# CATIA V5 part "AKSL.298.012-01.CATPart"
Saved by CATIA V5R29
Part number: АКСЛ.298.012-01
Publications: "Грань по длине шипа", "Грань по ширине шипа", "Грань по длине шипа1", "Грань по ширине шипа1"
Material "Steel": density 7860 kg/m3, Young's modulus 2e+11 Pa, Poisson ratio 0.266, thermal expansion 1.17e-05 1/K
Bounding box of the stored display mesh (mm): x -51 to 52, y -52 to 51, z -103 to 100
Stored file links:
  Z:\ООО Аксель\Соединения бруса\Соединения бруса\Соединения из листа\АКСЛ.298.010 (Основание)\AKSL.298.012-01.CATPart
  Z:\ООО Аксель\Соединения бруса\Соединения бруса\Соединения из листа\АКСЛ.298.010 (Основание)\AKSL.298.010.CATProduct
  Z:\#Catalog_GosNIIAS\Holes&Pockets\Part\Соединение шип-паз\Ship-Paz.CATPart
  298.012.CATPart
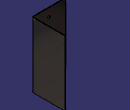
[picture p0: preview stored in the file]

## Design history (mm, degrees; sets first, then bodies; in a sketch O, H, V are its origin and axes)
External parameters (linked from other documents)
  `External.S металла` = 2 mm
  `External.R гиба` = 1.9 mm
  `External.K-factor` = 0.49
SheetMetalParameters1: Thickness 2 {= `External.S металла`}, BendRadius 1.9 {= `External.R гиба`}, KFactor 0.49 {= `External.K-factor`}, ReliefRadialLength 1, ReliefAxialLength 2, MinimumBendRadius 0
Set1 "Шип в центре грани"
  Extract1 "Плоскость шипа": ExtractElem face of Wall1
  Extract2 "Грань по длине шипа": ExtractElem edge of Extract1
  Extract3 "Грань по ширине шипа": ExtractElem edge of Extract1
Set2
  DatumCurve1 to DatumCurve3: linked copy from another document
  Plane1: linked copy from another document
Body1 (main body)
  Pad1: profile DatumCurve1, length 203, opposite side length -3, thin wall 0, second thickness 2 {= `External.S металла`}
  Recognize1: Recognize_BendTable SheetMetalParameters1, Recognize_ReferenceFace face of Pad1, Recognize_BendDefaultRadius 1.9 {= `External.R гиба`}, KFacteur 0.49 {= SheetMetalParameters1.KFactor}
  d_Bend1: Bend_BendTable SheetMetalParameters1, Bend_Thickness 2 {= `External.S металла`}, Bend_KFactor 0.49 {= SheetMetalParameters1.KFactor}, Bend_FirstSupport face of Recognize1, Bend_SecondSupport face of Recognize1, Bend_KFactorRadius 1.9 {= d_Bend1.CylindricalBendSurf_Radius}, Bend_Deduction -3.2761 {= (d_Bend1.CylindricalBendSurf_Radius+SheetMetalParameters1.Thickness*d_Bend1.Bend_KFactor)*(PI-abs(d_Bend1.BendSurf_OpenAngle))-2*(d_Bend1.CylindricalBendSurf_Radius+SheetMetalParameters1.Thickness)*tan(min((PI-abs(d_Bend1.BendSurf_OpenAngle)),(PI/2))/2)}
  CutOut1: Direction Sketch3, EndLimit through (limit type 2), Orientation true, Profile Sketch3, StartLimit through (limit type 2)
  CutOut2: Direction Sketch2, EndLimit through (limit type 2), Orientation true, Profile Sketch2, StartLimit through (limit type 2), Thickness1 2, Thickness2 2
  SHM_Mirror1: MirroringPlane Plane1, ObjectToMirror CutOut2
  Sketch1 on face of Recognize1, origin (13.3256, -52, 70.7942), H (1, 0, 0), V (0, 0, 1)
    point P1 (-12.3256, 4.2058)
    reference projected line E1 (-63.3256, -170.7942) -> (-63.3256, 29.2058) from edge [face of Recognize1 | face of Recognize1]
    reference projected line E2 (38.6744, -170.7942) -> (38.6744, 29.2058) from face of Recognize1
    construction line L1 (-63.3256, 29.2058) -> (38.6744, 29.2058)
    distance L1 P1 = 25
    horizontal: L1 H
    equidistance: E1 E2 P1
  Hole1: placed by Sketch1, at (1, -52, 75) direction (0, 1, 0), diameter 8, through (limit type 6)
  RectPattern1: of Hole1, direction 1 instances 3, spacing 50, along edge [face of Recognize1 | face of Recognize1] reversed
  Wall1: Thickness 2 {= `External.S металла`}, Profile Sketch4, ListTangentTo face of Recognize1, OffsetValue 0
  Wall2: Thickness 2 {= `External.S металла`}, Profile Sketch5, ListTangentTo face of Recognize1, OffsetValue 0
  Sketch2 on face of Recognize1, origin (52, 0, 0), H (0, 1, 0), V (0, 0, 1)
    reference projected line E2 (52, 100) -> (-48.1, 100) from edge [face of Recognize1 | face of Recognize1]
    point P5 (50, 90.5)
    point P6 (52, 90.5)
    construction line L1 (52, 100) -> (52, 90.5)
    line L2 (52, 90.5) -> (51, 90.5)
    line L3 (51, 90.5) -> (51, 100)
    line L4 (51, 100) -> (52, 100)
    line L5 (52, 100) -> (52, 90.5)
    point P8 (51, 100)
    vertical: L1 V, L3 V, L5 V
    horizontal: L2 H, L4 H
    coincidence: P8 E2
    symmetry: P5 P6 L3
  Sketch3 on DatumCurve2, origin (51, 50, 90), H (0, 0, -1), V (0, -1, 0)
    reference projected line E1 (0, -2) -> (0, 0) from DatumCurve3
    reference projected line E2 (0, 0) -> (180, 0) from DatumCurve2
    construction line L1 (0, -1) -> (90, -1)
    point P5 (0, -1)
    point P6 (90, -1)
    axis line L2 (90, 0) -> (90, 7.3468)
    point P7 (90, 0)
    line L3 (180.5, -2) -> (180.5, 0)
    line L4 (180.5, 0) -> (-0.5, 0)
    line L5 (-0.5, 0) -> (-0.5, -2)
    line L6 (-0.5, -2) -> (180.5, -2)
    distance L5 E1 = 0.5
    distance E2 L4 = 0
    midpoint: P5 E1, P7 E2
    coincidence: L2 P6
    equidistance: L3 L5 P6, L4 L6 P6
    parallelism: L1 E2, L2 E1, L6 L4, L3 L5
  Sketch4 on face of Recognize1, origin (-52, -52, 0), H (1, 0, 0), V (0, 0, 1)
    reference projected line E1 (2, -100) -> (2, 100) from edge [face of Recognize1 | face of Recognize1]
    line L1 (1, 90) -> (2, 90)
    line L2 (2, 90) -> (2, -90)
    line L3 (2, -90) -> (1, -90)
    line L4 (1, -90) -> (1, 90)
    axis line L5 (2, 0) -> (1, 0)
    point P7 (2, 0)
    point P8 (1, 0)
    distance L2 L4 = 1
    distance L1 L3 = 180
    length E1 = 200 (reference)
    perpendicularity: L2 L1
    midpoint: P7 L2, P8 L4, P7 E1
    coincidence: L2 E1
  Sketch5 on face of Recognize1, origin (-52, -52, 0), H (1, 0, 0), V (0, 0, 1)
    reference projected line E1 (100.1, -100) -> (2, -100) from edge [face of Recognize1 | face of Recognize1]
    line L1 (27, -103) -> (27, -100)
    line L2 (27, -100) -> (77, -100)
    line L3 (77, -100) -> (77, -103)
    line L4 (77, -103) -> (27, -103)
    axis line L5 (51.05, -100) -> (51.05, -103.1468)
    point P7 (51.05, -100)
    reference projected line E2 (104, -100) -> (104, 100) from face of Recognize1
    construction line L6 (2, -100) -> (2, -56)
    distance L2 L4 = 3
    distance L1 L3 = 50
    length E1 = 98.1 (reference)
    distance L3 E2 = 27
    perpendicularity: L2 L1
    midpoint: P7 E1
    coincidence: L2 E1
    vertical: L6 V, L5 V
  Set3 "Шип в центре грани"
    Extract4 "Плоскость шипа": ExtractElem face of Wall2
    Extract5 "Грань по длине шипа": ExtractElem edge of Extract4
    Extract6 "Грань по ширине шипа": ExtractElem edge of Extract4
